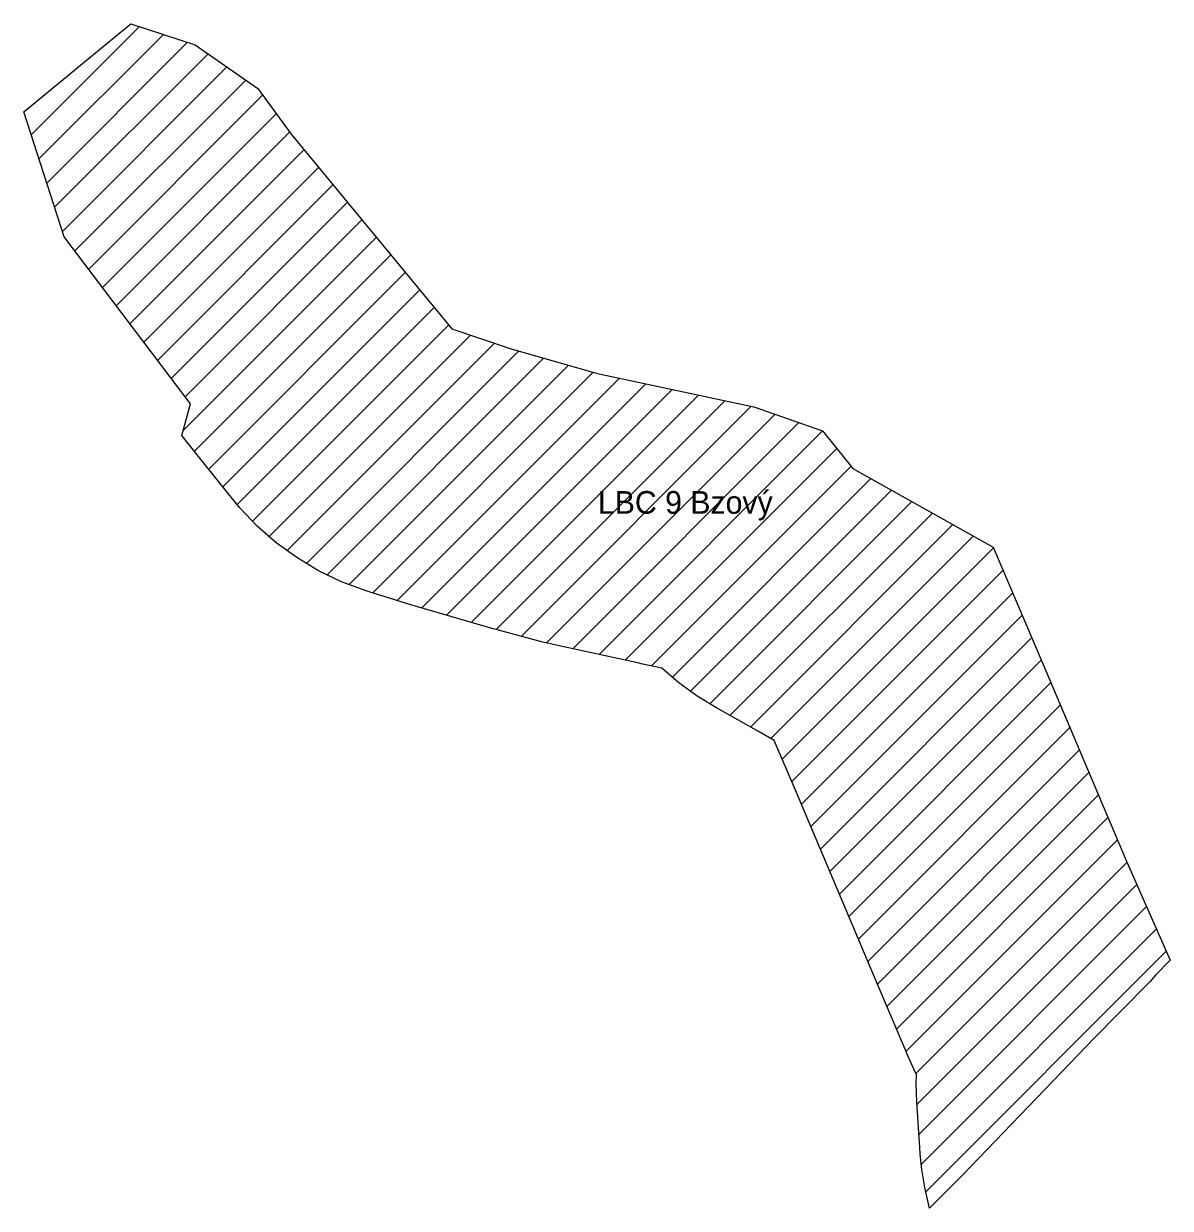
# Model space of a CAD drawing. Extents: x -477054 to -472307, y -1158904 to -1149471.
# Drawn here: x -477053.9 to -476648.2, y -1151596.3 to -1151177.4 of the extents above; entities that cross this region are included whole.
import ezdxf

# ---------------------------------------------------------------- set-up
doc = ezdxf.new("R2010")
doc.units = 0
doc.layers.add('16', color=7, linetype='Continuous')

msp = doc.modelspace()

# ---------------------------------------------------------------- linework, layer by layer
at = {"layer": '16'}
for p, q in [((-477051.21, -1151216.72), (-477012.93, -1151178.43)), ((-477048.44, -1151225.26), (-477004.41, -1151181.23)), ((-477045.68, -1151233.81), (-476995.89, -1151184.03)), ((-477042.91, -1151242.36), (-476988.65, -1151188.1)), ((-477040.14, -1151250.9), (-476981.99, -1151192.75)), ((-477035.73, -1151257.8), (-476975.32, -1151197.4)), ((-477030.86, -1151264.25), (-476969.35, -1151202.74)), ((-477025.99, -1151270.69), (-476964.58, -1151209.28)), ((-477021.12, -1151277.14), (-476959.81, -1151215.83)), ((-477016.25, -1151283.58), (-476954.72, -1151222.06)), ((-477011.38, -1151290.02), (-476949.6, -1151228.25)), ((-477006.51, -1151296.47), (-476944.48, -1151234.44)), ((-477001.64, -1151302.91), (-476939.36, -1151240.63)), ((-476996.77, -1151309.35), (-476934.23, -1151246.82)), ((-476997.41, -1151321.31), (-476929.11, -1151253.01)), ((-476993.4, -1151328.62), (-476923.99, -1151259.2)), ((-476988.4, -1151334.92), (-476918.87, -1151265.39)), ((-476983.39, -1151341.23), (-476913.75, -1151271.59)), ((-476978.33, -1151347.49), (-476908.62, -1151277.78)), ((-476972.87, -1151353.34), (-476903.5, -1151283.97)), ((-476966.98, -1151358.76), (-476895.76, -1151287.54)), ((-476960.64, -1151363.74), (-476887.3, -1151290.39)), ((-476953.84, -1151368.25), (-476878.73, -1151293.14)), ((-476946.54, -1151372.26), (-476869.94, -1151295.66)), ((-476938.71, -1151375.75), (-476861.14, -1151298.18)), ((-476930.36, -1151378.71), (-476852.35, -1151300.7)), ((-476921.72, -1151381.39), (-476843.09, -1151302.75)), ((-476913.04, -1151384.02), (-476833.77, -1151304.74)), ((-476904.27, -1151386.56), (-476824.45, -1151306.74)), ((-476895.5, -1151389.1), (-476815.13, -1151308.73)), ((-476886.72, -1151391.64), (-476805.81, -1151310.73)), ((-476877.8, -1151394.03), (-476796.49, -1151312.72)), ((-476868.86, -1151396.4), (-476787.99, -1151315.54)), ((-476859.62, -1151398.48), (-476779.59, -1151318.45)), ((-476850.32, -1151400.5), (-476771.22, -1151321.4)), ((-476841.03, -1151402.51), (-476766.18, -1151327.66)), ((-476831.7, -1151404.5), (-476761.13, -1151333.93)), ((-476824.35, -1151408.47), (-476754.14, -1151338.25)), ((-476818.01, -1151413.43), (-476746.89, -1151342.32)), ((-476811.17, -1151417.92), (-476739.64, -1151346.39)), ((-476804.01, -1151422.06), (-476732.4, -1151350.46)), ((-476796.76, -1151426.13), (-476725.15, -1151354.52)), ((-476789.51, -1151430.19), (-476717.91, -1151358.59)), ((-476785.5, -1151437.5), (-476710.76, -1151362.75)), ((-476782.09, -1151445.4), (-476707.37, -1151370.68)), ((-476778.71, -1151453.33), (-476703.99, -1151378.62)), ((-476775.36, -1151461.3), (-476700.61, -1151386.55)), ((-476772.01, -1151469.26), (-476697.22, -1151394.48)), ((-476768.65, -1151477.22), (-476693.84, -1151402.41)), ((-476765.29, -1151485.17), (-476690.46, -1151410.34)), ((-476761.93, -1151493.12), (-476687.09, -1151418.29)), ((-476758.57, -1151501.07), (-476683.73, -1151426.23)), ((-476755.2, -1151509.03), (-476680.36, -1151434.18)), ((-476751.84, -1151516.98), (-476676.99, -1151442.13)), ((-476748.48, -1151524.93), (-476673.63, -1151450.07)), ((-476745.12, -1151532.88), (-476670.26, -1151458.02)), ((-476741.76, -1151540.83), (-476666.89, -1151465.97)), ((-476738.24, -1151548.63), (-476663.52, -1151473.9)), ((-476737.89, -1151559.6), (-476660.05, -1151481.76)), ((-476737.19, -1151570.21), (-476656.59, -1151489.61)), ((-476736.3, -1151580.63), (-476653.13, -1151497.46)), ((-476734.75, -1151590.4), (-476649.67, -1151505.31))]:
    msp.add_line(p, q, dxfattribs=at)
msp.add_lwpolyline([(-476648.22, -1151508.59), (-476653.52, -1151513.83), (-476655.39, -1151516.06), (-476666.07, -1151526.9), (-476675.02, -1151535.98), (-476721.81, -1151584.64), (-476733.41, -1151596.27), (-476735.08, -1151588.95), (-476735.66, -1151585.42), (-476736.08, -1151582.52), (-476736.71, -1151577.15), (-476736.89, -1151574.78), (-476737.95, -1151558.72), (-476738.17, -1151552.13), (-476738.03, -1151549.06), (-476738.88, -1151547.35), (-476740.89, -1151542.89), (-476752.86, -1151514.57), (-476769.86, -1151474.36), (-476780.76, -1151448.46), (-476788.39, -1151430.82), (-476793.67, -1151427.86), (-476808.82, -1151419.36), (-476815.61, -1151415.19), (-476822.03, -1151410.48), (-476828.05, -1151405.26), (-476835.36, -1151403.74), (-476836.16, -1151403.57), (-476865.54, -1151397.2), (-476866.6, -1151396.96), (-476870.23, -1151396.06), (-476885.83, -1151391.88), (-476887.78, -1151391.34), (-476914.87, -1151383.49), (-476916.6, -1151382.97), (-476931.69, -1151378.3), (-476933.03, -1151377.88), (-476941.43, -1151374.72), (-476949.52, -1151370.83), (-476957.22, -1151366.23), (-476964.48, -1151360.95), (-476971.24, -1151355.05), (-476977.44, -1151348.56), (-476980.5, -1151344.89), (-476991.96, -1151330.42), (-476997.87, -1151323.02), (-476994.87, -1151311.86), (-477039.54, -1151252.77), (-477053.86, -1151208.55), (-477027.02, -1151186.54), (-477015.93, -1151177.45), (-476993.23, -1151184.9), (-476971.08, -1151200.36), (-476959.28, -1151216.55), (-476902.39, -1151285.31), (-476881.46, -1151292.36), (-476851.32, -1151300.99), (-476849.24, -1151301.43), (-476795.5, -1151312.93), (-476771.26, -1151321.35), (-476760.55, -1151334.65), (-476710.84, -1151362.56), (-476691.14, -1151408.74), (-476663.8, -1151473.26)], close=True, dxfattribs=at)

# ---------------------------------------------------------------- texts
msp.add_text('LBC 9 Bzový', height=8, dxfattribs=at).set_placement((-476850.72, -1151350.69))

doc.saveas('drawing.dxf')
